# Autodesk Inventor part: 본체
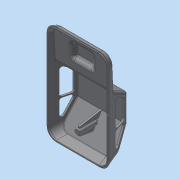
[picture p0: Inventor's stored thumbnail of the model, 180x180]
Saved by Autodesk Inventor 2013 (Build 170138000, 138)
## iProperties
Created: 2015-05
Part Number: 본체
Material: 일반
Document SubType Name: Modeling
Designer: Administrator
Density: 1 g/cm^3
Author: Administrator
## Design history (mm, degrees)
sketch "스케치2"
  geometry: L1 (-38, 31)-(38, 31); L2 (38, 31)-(38, 0); L3 (38, 0)-(-38, 0); L4 (-38, 0)-(-38, 31); 2 further points
  constraints: 8 end point, 2 parallel, 1 coincident, 1 horizontal, 1 midpoint, 1 perpendicular
  dimensions: "d9" = 76 distance of L2.end L3.end; "d11" = 31 distance of L1.end L2.end
extrude "돌출1" new body sketch "스케치2" stored distance "d12" = 122; taper "d13" = 0 deg
sketch "스케치3"
  geometry: L1 (38, 31)-(-38, 31) reference; L2 (-38, 31)-(-38, 0) reference; L3 (-38, 0)-(38, 0) reference; L4 (38, 0)-(38, 31) reference; L5 (-38, 0)-(-37, 0); L6 (-37, 0)-(-37, 1); L7 (-37, 1)-(-38, 1); L8 (-38, 1)-(-38, 0); L9 (38, 0)-(37, 0); L10 (37, 0)-(37, 1); L11 (37, 1)-(38, 1); L12 (38, 1)-(38, 0); L13 (-38, 1)-(-29.962, 31); L14 (38, 1)-(29.962, 31); 1 further point
  constraints: 20 end point, 4 parallel, 2 horizontal, 2 perpendicular, 2 point on line
  dimensions: "d14" = 1 distance of L10.end L11.end; "d16" = 1 distance of L9.end L10.end; "d17" = 1 distance of L6.end L7.end; "d18" = 1 distance of L5.end L6.end; "d19" = 105 deg angle of L3 L14; "d20" = 105 deg angle of L3 L13
node "작업 평면1"
extrude "돌출3" cut sketch "스케치3" distance "d24" = 122; taper "d25" = 0 deg
sketch "스케치5"
  geometry: L1 (1, 61)-(31, 61) reference; L2 (31, 61)-(31, -61) reference; L3 (31, -61)-(1, -61) reference; L4 (0, 61)-(0, -61) reference; L5 (1, 61)-(7, 59.392); L6 (7, 59.392)-(9.117, 19); L7 (9.117, 19)-(31, 5.326); L8 (31, -27.805)-(11, -61); L9 (12.925, -57.805)-(1, -61); L10 (0, 61)-(1, 61); L11 (1, 61)-(1, 60); L12 (1, 60)-(0, 60); L13 (0, 60)-(0, 61); L14 (0, -61)-(1, -61); L15 (1, -61)-(1, -60); L16 (1, -60)-(0, -60); L17 (0, -60)-(0, -61); L18 (1, -61)-(1, 61) reference; 1 further point
  constraints: 26 end point, 4 parallel, 4 point on line, 2 horizontal, 2 perpendicular
  dimensions: "d26" = 1 distance of L14.end L15.end; "d28" = 1 distance of L10.end L11.end; "d29" = 6 horizontal distance of L5.end L1.start; "d30" = 42 vertical distance of L6.end L1.start; "d31" = 105 deg angle of L4 L5; "d32" = 3 deg angle of L18 L6; "d33" = 125 deg angle of L7 L6; "d35" = 20 distance of L2.end L8.end; "d36" = 30 vertical distance of L9.start L8.start; "d37" = 105 deg angle of L4 L9
extrude "돌출4" cut sketch "스케치5" stored distance "d38" = 122; taper "d39" = 0 deg
sketch "스케치6"
  geometry: L1 (7, 59.392)-(9.117, 19) reference; L2 (1, 61)-(7, 59.392) reference; L3 (7.475, 50.324)-(8.522, 30.352); L4 (1, 61)-(20.944, 62.045); L5 (0, 61)-(0, -61) reference; L6 (7.475, 50.324)-(12.564, 48.769); L7 (8.522, 30.352)-(13.42, 32.431); L8 (12.564, 48.769)-(13.42, 32.431); 1 further point
  constraints: 10 end point, 2 point on line, 1 parallel
  dimensions: "d40" = 20 distance of L3.start L3.end; "d41" = 87 deg angle of L5 L4; "d43" = 11 distance from line of L3.start L4; "d44" = 70 deg angle of L1 L6; "d45" = 70 deg angle of L1 L7; "d46" = 5 distance between parallel lines of L1 L8
extrude "돌출5" join sketch "스케치6" stored distance "d47" = 26; taper "d48" = 0 deg
extrude "돌출6" cut sketch "스케치3" stored distance "d49" = 26; taper "d50" = 0 deg
extrude "돌출7" join sketch "스케치5" stored distance "d51" = 26; taper "d52" = 0 deg
extrude "돌출8" cut sketch "스케치5" stored distance "d53" = 26; taper "d54" = 0 deg
fillet "모깎기1" dims "d55" = 12
fillet "모깎기2" dims "d56" = 12
fillet "모깎기3" dims "d57" = 12
fillet "모깎기4" dims "d58" = 12
fillet "모깎기5" dims "d59" = 3
fillet "모깎기6" dims "d60" = 3
fillet "모깎기7" dims "d61" = 3
feature "쉘1" dims "d62" = 1, "d63" = 2
sketch "스케치8"
  geometry: 1 further point
sketch "스케치9"
  geometry: L1 (29.59, 6.207)-(10.441, 18.172) reference; L2 (31, -26.971)-(31, 3.663) reference; L3 (19.796, -46.401)-(30.57, -28.519) reference; L4 (15.59, 9.059)-(24.59, 3.436); L5 (26, 0.891)-(26, -19.073); L6 (11, -19.073)-(11, 6.515); L7 (0, -48)-(0, 48) reference; L8 (23, -22.073)-(14, -22.073); L9 (26, -26.415)-(16.57, -42.067); L10 (11, -40.519)-(11, -26.311); L11 (14, -23.311)-(23, -23.311); L12 (26, -26.415)-(26, -26.311); A1 r 3 centre (28, 3.663) between (31, 3.663) and (29.59, 6.207) reference; A2 r 3 centre (28, -26.971) between (30.57, -28.519) and (31, -26.971) reference; A3 r 3 centre (14, 6.515) between (15.59, 9.059) and (11, 6.515); A4 r 3 centre (23, 0.891) between (26, 0.891) and (24.59, 3.436); A5 r 3 centre (23, -19.073) between (23, -22.073) and (26, -19.073); A6 r 3 centre (14, -19.073) between (11, -19.073) and (14, -22.073); A7 r 3 centre (14, -26.311) between (14, -23.311) and (11, -26.311); A8 r 3 centre (23, -26.311) between (26, -26.311) and (23, -23.311); A9 r 3 centre (14, -40.519) between (11, -40.519) and (16.57, -42.067); 5 further points
  constraints: 16 end point, 14 point on circle, 14 tangent, 8 point on line, 7 centre point, 4 equal radius, 4 parallel, 4 perpendicular
  dimensions: "d65" = 5 distance between parallel lines of L1 L4; "d66" = 5 distance between parallel lines of L2 L5; "d67" = 15 distance between parallel lines of L5 L6; "d68" = 34 distance of point (11, -22.073) point (11, 11.927); "d69" = 5 distance between parallel lines of L9 L3; "d70" = 5 distance from line of L2 L9.start; "d71" = 15 horizontal distance of point (11, -51.311) L9.start; "d72" = 28 distance of point (11, -51.311) point (11, -23.311); "d73" = 3 radius of A3; "d74" = 3 radius of A7; "d75" = 3 radius of A9
extrude "돌출9" cut sketch "스케치9" stored distance "d76" = 26; taper "d77" = 0 deg
fillet "모깎기8" dims "d78" = 3
fillet "모깎기9" dims "d79" = 3
sketch "스케치10"
  geometry: L1 (29, 3.663)-(29, -26.971) reference; L2 (28.857, -27.487)-(18.083, -45.369) reference; L3 (18.083, -45.369)-(11.837, -55.736) reference; L4 (29, -26.971)-(2, -31.732); L5 (2, -31.732)-(2, -33.732); L6 (25.094, -33.732)-(0, -33.732); L7 (0, -33.732)-(0, -39.732); L8 (0, -39.732)-(21.479, -39.732); L9 (2, -39.732)-(2, -41.732); L10 (2, -41.732)-(18.519, -44.644); L11 (0, -48)-(0, 48) reference; L12 (0, -36.732)-(23.287, -36.732); L13 (21.479, -39.732)-(18.519, -44.644); A1 r 1 centre (28, -26.971) between (28.857, -27.487) and (29, -26.971) reference; 1 further point
  constraints: 18 end point, 7 point on line, 3 parallel, 3 perpendicular, 1 collinear, 1 midpoint
  dimensions: "d80" = 10 distance of L9.end L4.end; "d82" = 2 distance from line of L4.end L6; "d83" = 2 distance from line of L8 L9.end; "d85" = 80 deg angle of L11 L4; "d88" = 80 deg angle of L11 L10; "d89" = 2 distance of L6.end L5.end; "d90" = 2 distance of L7.end L9.start
revolve "회전1" stored, may be unused: angle "d91" = 90 deg
extrude "돌출10" join sketch "스케치10" stored distance "d92" = 2; taper "d93" = 0 deg
extrude "돌출11" join sketch "스케치10" stored distance "d94" = 2; taper "d95" = -4 deg
sketch "스케치11"
  geometry: C1 r 3 at (0, 0) reference; C2 r 3 at (0, 0); 1 further point
  constraints: 1 centre point, 1 coincident, 1 concentric
extrude "돌출12" join sketch "스케치11" stored distance "d96" = 2; taper "d97" = -4 deg
node "솔리드1"
other parameters: "d23" = 38
